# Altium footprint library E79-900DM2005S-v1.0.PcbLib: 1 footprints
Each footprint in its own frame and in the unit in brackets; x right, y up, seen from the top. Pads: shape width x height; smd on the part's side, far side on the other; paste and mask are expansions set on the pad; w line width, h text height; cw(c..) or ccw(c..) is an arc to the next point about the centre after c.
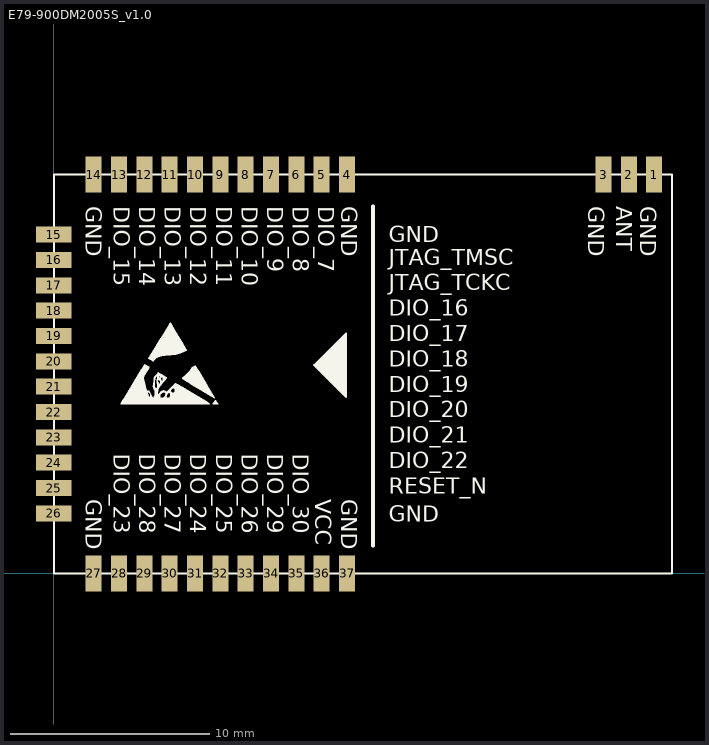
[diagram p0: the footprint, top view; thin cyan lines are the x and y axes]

## E79-900DM2005S_v1.0 [mil]
pads (1585):
  round 0.5 on Top Overlay: 1(132.13,335.44) 1(132.63,335.94) 1(132.63,336.44) 1(133.13,336.94) 1(133.13,337.44) 1(133.63,337.94) 1(134.13,338.44) 1(134.13,338.94) 1(134.63,339.44) 1(134.63,339.94) 1(135.13,340.44) 1(135.63,341.44) 1(135.63,340.94) 1(136.13,341.94) 1(136.13,342.44) 1(136.63,342.94) 1(137.13,343.44) 1(137.13,343.94) 1(137.63,344.44) 1(137.63,344.94) 1(138.13,345.44) 1(138.63,345.94) 1(138.63,346.44) 1(139.13,346.94) 1(139.63,347.94) 1(139.63,347.44) 1(140.13,348.44) 1(140.13,348.94) 1(140.63,349.44) 1(141.13,349.94) 1(141.13,350.44) 1(141.63,350.94) 1(141.63,351.44) 1(142.13,351.94) 1(142.63,352.44) 1(142.63,352.94) 1(143.13,353.44) 1(143.13,353.94) 1(143.63,354.44) 1(144.13,354.94) 1(144.13,355.44) 1(144.63,355.94) 1(144.63,356.44) 1(145.13,356.94) 1(145.63,357.44) 1(145.63,357.94) 1(146.13,358.44) 1(146.13,358.94) 1(146.63,359.44) 1(147.13,359.94) 1(147.13,360.44) 1(147.63,360.94) 1(147.63,361.44) 1(148.13,361.94) 1(148.63,362.44) 1(148.63,362.94) 1(149.13,363.44) 1(149.13,363.94) 1(149.63,364.44) 1(150.13,365.44) 1(150.13,364.94) 1(150.63,365.94) 1(150.63,366.44) 1(151.13,366.94) 1(151.63,367.44) 1(151.63,367.94) 1(152.13,368.44) 1(152.13,368.94) 1(152.63,369.44) 1(153.13,369.94) 1(153.13,370.44) 1(153.63,370.94) 1(153.63,371.44) 1(154.13,371.94) 1(154.63,372.44) 1(154.63,372.94) 1(155.13,373.44) 1(155.13,373.94) 1(155.63,374.44) 1(156.13,375.44) 1(156.13,374.94) 1(156.63,375.94) 1(156.63,376.44) 1(157.13,376.94) 1(157.63,377.44) 1(157.63,377.94) 1(158.13,378.44) 1(158.63,378.94) 1(158.63,379.44) 1(159.13,379.94) 1(159.13,380.44) 1(159.63,380.94) 1(160.13,381.44) 1(160.13,381.94) 1(160.63,382.44) 1(160.63,382.94) 1(161.13,383.44) 1(161.63,383.94) 1(161.63,384.44) 1(162.13,384.94) 1(162.13,385.44) 1(162.63,385.94) 1(163.13,386.44) 1(163.13,386.94) 1(163.63,387.44) 1(163.63,387.94) 1(164.13,388.44) 1(164.63,389.44) 1(164.63,388.94) 1(165.13,389.94) 1(165.13,390.44) 1(165.63,390.94) 1(166.13,391.44) 1(166.13,391.94) 1(166.63,392.44) 1(166.63,392.94) 1(167.13,393.44) 1(167.63,393.94) 1(167.63,394.44) 1(168.13,394.94) 1(168.13,395.44) 1(168.63,395.94) 1(169.13,396.44) 1(169.13,396.94) 1(169.63,397.94) 1(169.63,397.44) 1(170.13,398.44) 1(170.63,398.94) 1(170.63,399.44) 1(171.13,399.94) 1(171.63,400.44) 1(171.63,400.94) 1(172.13,401.44) 1(172.13,401.94) 1(172.63,402.44) 1(173.13,402.94) 1(173.13,403.44) 1(173.63,403.94) 1(173.63,404.44) 1(174.13,404.94) 1(174.63,405.44) 1(174.63,405.94) 1(175.13,406.44) 1(175.13,406.94) 1(175.63,407.44) 1(176.13,407.94) 1(176.13,408.44) 1(176.63,408.94) 1(176.63,409.44) 1(177.13,409.94) 1(177.63,382.94) 1(177.63,383.44) 1(177.63,383.94) 1(177.63,384.44) 1(177.63,384.94) 1(177.63,385.44) 1(177.63,385.94) 1(177.63,386.44) 1(177.63,386.94) 1(177.63,387.44) 1(177.63,387.94) 1(177.63,388.44) 1(177.63,388.94) 1(177.63,410.44) 1(177.63,410.94) 1(178.13,380.44) 1(178.13,380.94) 1(178.13,381.44) 1(178.13,381.94) 1(178.13,382.44) 1(178.13,389.44) 1(178.13,389.94) 1(178.13,390.44) 1(178.13,411.44) 1(178.13,411.94) 1(178.63,378.44) 1(178.63,378.94) 1(178.63,379.44) 1(178.63,379.94) 1(178.63,390.94) 1(178.63,391.44) 1(178.63,412.44) 1(179.13,376.94) 1(179.13,377.44) 1(179.13,377.94) 1(179.13,391.94) 1(179.13,392.44) 1(179.13,412.94) 1(179.63,375.44) 1(179.63,376.44) 1(179.63,392.94) 1(179.63,412.94) 1(179.63,374.94) 1(179.63,375.94) 1(180.13,372.94) 1(180.13,373.94) 1(180.13,393.44) 1(180.13,393.94) 1(180.13,373.44) 1(180.13,374.44) 1(180.63,370.94) 1(180.63,371.44) 1(180.63,371.94) 1(180.63,372.44) 1(180.63,394.44) 1(180.63,412.44) 1(181.13,368.94) 1(181.13,369.44) 1(181.13,369.94) 1(181.13,370.44) 1(181.13,394.94) 1(181.13,395.44) 1(181.13,411.94) 1(181.63,366.44) 1(181.63,366.94) 1(181.63,367.44) 1(181.63,367.94) 1(181.63,368.44) 1(181.63,395.94) 1(181.63,396.44) 1(182.13,364.94) 1(182.13,365.44) 1(182.13,365.94) 1(182.13,396.94) 1(182.13,411.44) 1(182.63,362.94) 1(182.63,363.44) 1(182.63,363.94) 1(182.63,364.44) 1(182.63,397.44) 1(182.63,397.94) 1(183.13,361.94) 1(183.13,362.44) 1(183.13,398.44) 1(183.13,410.94) 1(183.63,361.44) 1(183.63,398.94) 1(183.63,399.44) 1(183.63,410.44) 1(184.13,399.94) 1(184.63,400.44) 1(184.63,400.94) 1(184.63,409.94) 1(185.13,401.44) 1(185.63,354.44) 1(185.63,354.94) 1(185.63,355.44) 1(185.63,355.94) 1(185.63,356.44) 1(185.63,356.94) 1(185.63,357.44) 1(185.63,357.94) 1(185.63,401.94) 1(185.63,402.44) 1(185.63,409.44) 1(186.13,352.44) 1(186.13,352.94) 1(186.13,353.44) 1(186.13,353.94) 1(186.13,358.44) 1(186.13,358.94) 1(186.13,402.94) 1(186.13,408.94) 1(186.63,351.44) 1(186.63,351.94) 1(186.63,358.94) 1(186.63,403.94) 1(186.63,424.94) 1(186.63,403.44) 1(187.13,350.44) 1(187.13,350.94) 1(187.13,404.44) 1(187.13,408.44) 1(187.13,424.44) 1(187.13,425.44) 1(187.63,349.44) 1(187.63,349.94) 1(187.63,358.44) 1(187.63,404.94) 1(187.63,405.44) 1(187.63,425.94) 1(187.63,426.44) 1(188.13,357.94) 1(188.13,360.44) 1(188.13,360.94) 1(188.13,405.94) 1(188.13,406.44) 1(188.13,407.94) 1(188.13,423.94) 1(188.13,426.94) 1(188.63,357.44) 1(188.63,359.44) 1(188.63,359.94) 1(188.63,406.94) 1(188.63,407.44) 1(188.63,427.44) 1(188.63,427.94) 1(189.13,356.44) 1(189.13,356.94) 1(189.13,358.44) 1(189.13,358.94) 1(189.13,428.44) 1(189.13,428.94) 1(189.63,355.44) 1(189.63,355.94) 1(189.63,357.44) 1(189.63,357.94) 1(189.63,423.44) 1(189.63,429.44) 1(190.13,349.44) 1(190.13,349.94) 1(190.13,354.44) 1(190.13,354.94) 1(190.13,356.44) 1(190.13,356.94) 1(190.13,429.94) 1(190.13,430.44) 1(190.63,350.44) 1(190.63,353.94) 1(190.63,355.94) 1(190.63,350.94) 1(190.63,351.44) 1(190.63,351.94) 1(190.63,352.44) 1(190.63,352.94) 1(190.63,353.44) 1(190.63,355.44) 1(190.63,422.94) 1(190.63,430.94) 1(190.63,431.44) 1(191.13,354.44) 1(191.13,353.94) 1(191.13,354.94) 1(191.13,431.94) 1(191.63,432.94) 1(191.63,352.94) 1(191.63,353.44) 1(191.63,422.44) 1(191.63,432.44) 1(192.13,433.44) 1(192.13,351.94) 1(192.13,352.44) 1(192.13,421.94) 1(192.63,433.94) 1(192.63,350.94) 1(192.63,351.44) 1(192.63,434.44) 1(193.13,350.44) 1(193.13,421.44) 1(193.13,434.94) 1(193.13,435.44) 1(193.63,349.94) 1(193.63,435.94) 1(193.63,349.44) 1(194.13,348.44) 1(194.13,420.94) 1(194.13,436.44) 1(194.13,436.94) 1(194.13,348.94) 1(194.63,347.94) 1(194.63,420.44) 1(194.63,437.44) 1(194.63,437.94) 1(195.13,347.44) 1(195.13,438.44) 1(195.63,346.94) 1(195.63,369.94) 1(195.63,370.44) 1(195.63,370.94) 1(195.63,419.94) 1(195.63,438.94) 1(195.63,439.44) 1(196.13,367.94) 1(196.13,368.44) 1(196.13,368.94) 1(196.13,369.44) 1(196.13,371.44) 1(196.13,371.94) 1(196.13,372.44) 1(196.13,372.94) 1(196.13,373.44) 1(196.13,373.94) 1(196.13,439.94) 1(196.13,440.44) 1(196.63,346.94) 1(196.63,366.94) 1(196.63,367.44) 1(196.63,374.44) 1(196.63,374.94) 1(196.63,375.44) 1(196.63,375.94) 1(196.63,376.44) 1(196.63,440.94) 1(197.13,347.44) 1(197.13,347.94) 1(197.13,365.94) 1(197.13,366.44) 1(197.13,376.94) 1(197.13,377.44) 1(197.13,377.94) 1(197.13,378.44) 1(197.13,378.94) 1(197.13,379.44) 1(197.13,379.94) 1(197.13,380.44) 1(197.13,380.94) 1(197.13,381.44) 1(197.13,381.94) 1(197.13,382.44) 1(197.13,382.94) 1(197.13,383.44) 1(197.13,383.94) 1(197.13,384.44) 1(197.13,384.94) 1(197.13,419.94) 1(197.13,441.44) 1(197.13,441.94) 1(197.63,348.44) 1(197.63,364.94) 1(197.63,365.44) 1(197.63,385.44) 1(197.63,385.94) 1(197.63,386.44) 1(197.63,420.44) 1(197.63,420.94) 1(197.63,442.44) 1(198.13,349.44) 1(198.13,364.44) 1(198.13,348.94) 1(198.13,363.94) 1(198.13,386.94) 1(198.13,387.44) 1(198.13,421.44) 1(198.13,421.94) 1(198.13,442.94) 1(198.13,443.44) 1(198.63,349.94) 1(198.63,362.94) 1(198.63,350.44) 1(198.63,363.44) 1(198.63,387.94) 1(198.63,422.44) 1(198.63,443.94) 1(198.63,444.44) 1(199.13,362.44) 1(199.13,374.94) 1(199.13,375.94) 1(199.13,350.94) 1(199.13,351.44) 1(199.13,351.94) 1(199.13,352.44) 1(199.13,352.94) 1(199.13,361.44) 1(199.13,361.94) 1(199.13,368.94) 1(199.13,369.44) 1(199.13,369.94) 1(199.13,370.44) 1(199.13,370.94) 1(199.13,371.44) 1(199.13,371.94) 1(199.13,372.44) 1(199.13,372.94) 1(199.13,373.44) 1(199.13,373.94) 1(199.13,374.44) 1(199.13,375.44) 1(199.13,376.44) 1(199.13,376.94) 1(199.13,377.44) 1(199.13,377.94) 1(199.13,388.44) 1(199.13,422.94) 1(199.13,444.94) 1(199.63,356.44) 1(199.63,367.94) 1(199.63,381.94) 1(199.63,353.44) 1(199.63,353.94) 1(199.63,354.44) 1(199.63,354.94) 1(199.63,355.44) 1(199.63,355.94) 1(199.63,356.94) 1(199.63,357.44) 1(199.63,358.44) 1(199.63,358.94) 1(199.63,359.44) 1(199.63,359.94) 1(199.63,360.44) 1(199.63,360.94) 1(199.63,368.44) 1(199.63,378.44) 1(199.63,378.94) 1(199.63,379.44) 1(199.63,379.94) 1(199.63,380.44) 1(199.63,380.94) 1(199.63,381.44) 1(199.63,382.44) 1(199.63,382.94) 1(199.63,388.94) 1(199.63,423.44) 1(199.63,445.44) 1(199.63,445.94) 1(200.13,357.94) 1(200.13,366.94) 1(200.13,367.44) 1(200.13,383.44) 1(200.13,383.94) 1(200.13,384.44) 1(200.13,384.94) 1(200.13,385.44) 1(200.13,389.44) 1(200.13,423.94) 1(200.13,446.44) 1(200.63,366.44) 1(200.63,385.94) 1(200.63,386.44) 1(200.63,386.94) 1(200.63,389.94) 1(200.63,424.44) 1(200.63,446.94) 1(200.63,447.44) 1(201.13,365.94) 1(201.13,387.44) 1(201.13,387.94) 1(201.13,390.44) 1(201.13,424.94) 1(201.13,448.44) 1(201.13,447.94) 1(201.63,390.94) 1(201.63,425.44) 1(201.63,448.94) 1(201.63,388.44) 1(202.13,391.44) 1(202.13,449.44) 1(202.13,388.94) 1(202.13,449.94) 1(202.63,389.44) 1(202.63,391.94) 1(202.63,425.94) 1(202.63,450.44) 1(202.63,450.94) 1(203.13,365.94) 1(203.13,389.94) 1(203.13,392.44) 1(203.13,426.44) 1(203.13,451.44) 1(203.63,366.44) 1(203.63,366.94) 1(203.63,375.94) 1(203.63,376.44) 1(203.63,376.94) 1(203.63,377.44) 1(203.63,377.94) 1(203.63,378.44) 1(203.63,378.94) 1(203.63,379.44) 1(203.63,379.94) 1(203.63,380.44) 1(203.63,380.94) 1(203.63,381.44) 1(203.63,381.94) 1(203.63,382.44) 1(203.63,382.94) 1(203.63,392.94) 1(203.63,451.94) 1(203.63,452.44) 1(204.13,367.44) 1(204.13,367.94) 1(204.13,368.44) 1(204.13,368.94) 1(204.13,369.44) 1(204.13,369.94) 1(204.13,370.44) 1(204.13,370.94) 1(204.13,371.94) 1(204.13,372.44) 1(204.13,372.94) 1(204.13,373.44) 1(204.13,373.94) 1(204.13,374.44) 1(204.13,374.94) 1(204.13,375.44) 1(204.13,383.44) 1(204.13,383.94) 1(204.13,384.44) 1(204.13,384.94) 1(204.13,385.44) 1(204.13,385.94) 1(204.13,386.44) 1(204.13,388.94) 1(204.13,389.44) 1(204.13,389.94) 1(204.13,393.44) 1(204.13,393.94) 1(204.13,426.94) 1(204.13,452.94) 1(204.13,453.44) 1(204.63,371.44) 1(204.63,386.94) 1(204.63,387.44) 1(204.63,387.94) 1(204.63,388.44) 1(204.63,394.44) 1(204.63,453.94) 1(205.13,379.94) 1(205.13,394.94) 1(205.13,395.44) 1(205.13,427.44) 1(205.13,454.44) 1(205.13,454.94) 1(205.63,354.94) 1(205.63,355.94) 1(205.63,356.94) 1(205.63,381.44) 1(205.63,396.44) 1(205.63,455.44) 1(205.63,354.44) 1(205.63,355.44) 1(205.63,356.44) 1(205.63,357.44) 1(205.63,357.94) 1(205.63,358.44) 1(205.63,358.94) 1(205.63,359.44) 1(205.63,359.94) 1(205.63,377.94) 1(205.63,378.44) 1(205.63,378.94) 1(205.63,379.44) 1(205.63,380.44) 1(205.63,380.94) 1(205.63,381.94) 1(205.63,395.94) 1(205.63,396.94) 1(206.13,362.94) 1(206.13,396.94) 1(206.13,455.94) 1(206.13,353.94) 1(206.13,360.44) 1(206.13,360.94) 1(206.13,361.44) 1(206.13,361.94) 1(206.13,362.44) 1(206.13,376.94) 1(206.13,377.44) 1(206.13,382.44) 1(206.13,456.44) 1(206.63,363.44) 1(206.63,396.44) 1(206.63,353.94) 1(206.63,363.94) 1(206.63,364.44) 1(206.63,364.94) 1(206.63,376.44) 1(206.63,427.94) 1(206.63,456.94) 1(206.63,457.44) 1(207.13,389.44) 1(207.13,365.44) 1(207.13,365.94) 1(207.13,375.44) 1(207.13,375.94) 1(207.13,387.44) 1(207.13,387.94) 1(207.13,388.44) 1(207.13,388.94) 1(207.13,457.94) 1(207.63,354.44) 1(207.63,366.44) 1(207.63,366.94) 1(207.63,386.94) 1(207.63,389.94) 1(207.63,390.44) 1(207.63,395.94) 1(207.63,428.44) 1(207.63,458.44) 1(207.63,458.94) 1(208.13,354.94) 1(208.13,367.44) 1(208.13,459.44) 1(208.13,367.94) 1(208.63,355.44) 1(208.63,368.94) 1(208.63,390.94) 1(208.63,395.44) 1(208.63,459.94) 1(208.63,460.44) 1(208.63,368.44) 1(208.63,382.44) 1(209.13,355.94) 1(209.13,369.44) 1(209.13,369.94) 1(209.13,386.94) 1(209.13,387.44) 1(209.13,390.94) 1(209.13,428.94) 1(209.13,460.94) 1(209.13,461.44) 1(209.13,381.94) 1(209.63,356.44) 1(209.63,370.44) 1(209.63,388.44) 1(209.63,389.44) 1(209.63,390.44) 1(209.63,394.94) 1(209.63,350.44) 1(209.63,356.94) 1(209.63,381.44) 1(209.63,387.94) 1(209.63,388.94) 1(209.63,389.94) 1(209.63,461.94) 1(210.13,346.94) 1(210.13,347.94) 1(210.13,348.94) 1(210.13,349.94) 1(210.13,357.44) 1(210.13,375.44) 1(210.13,380.94) 1(210.13,462.44) 1(210.13,347.44) 1(210.13,348.44) 1(210.13,349.44) 1(210.13,350.94) 1(210.13,351.44) 1(210.13,351.94) 1(210.13,352.44) 1(210.13,352.94) 1(210.13,370.94) 1(210.13,371.44) 1(210.13,380.44) 1(210.13,394.44) 1(210.13,462.94) 1(210.63,375.94) 1(210.63,463.94) 1(210.63,353.44) 1(210.63,353.94) 1(210.63,357.94) 1(210.63,358.44) 1(210.63,371.94) 1(210.63,376.44) 1(210.63,376.94) 1(210.63,379.44) 1(210.63,379.94) 1(210.63,463.44) 1(211.13,382.94) 1(211.13,354.44) 1(211.13,354.94) 1(211.13,358.94) 1(211.13,372.44) 1(211.13,377.44) 1(211.13,377.94) 1(211.13,378.44) 1(211.13,378.94) 1(211.13,383.44) 1(211.13,383.94) 1(211.13,384.44) 1(211.13,384.94) 1(211.13,385.44) 1(211.13,385.94) 1(211.13,386.44) 1(211.13,393.94) 1(211.13,429.44) 1(211.13,464.44) 1(211.63,382.44) 1(211.63,355.44) 1(211.63,359.44) 1(211.63,372.94) 1(211.63,373.44) 1(211.63,381.94) 1(211.63,386.94) 1(211.63,387.44) 1(211.63,464.94) 1(211.63,465.44) 1(212.13,355.94) 1(212.13,359.94) 1(212.13,373.94) 1(212.13,380.94) 1(212.13,381.44) 1(212.13,393.44) 1(212.13,465.94) 1(212.13,466.44) 1(212.63,356.44) 1(212.63,360.44) 1(212.63,374.44) 1(212.63,392.94) 1(212.63,466.94) 1(213.13,356.94) 1(213.13,360.94) 1(213.13,374.94) 1(213.13,380.44) 1(213.13,387.94) 1(213.13,429.94) 1(213.13,467.44) 1(213.13,467.94) 1(213.63,375.44) 1(213.63,392.44) 1(213.63,468.44) 1(214.13,357.44) 1(214.13,375.94) 1(214.13,376.44) 1(214.13,468.94) 1(214.13,469.44) 1(214.63,376.94) 1(214.63,380.44) 1(214.63,380.94) 1(214.63,381.44) 1(214.63,381.94) 1(214.63,382.44) 1(214.63,382.94) 1(214.63,383.44) 1(214.63,383.94) 1(214.63,384.44) 1(214.63,384.94) 1(214.63,385.44) 1(214.63,385.94) 1(214.63,386.44) 1(214.63,387.94) 1(214.63,391.94) 1(214.63,469.94) 1(214.63,470.44) 1(215.13,357.94) 1(215.13,377.44) 1(215.13,386.94) 1(215.13,387.44) 1(215.13,391.44) 1(215.13,470.94) 1(215.63,346.94) 1(215.63,361.44) 1(215.63,377.94) 1(215.63,471.44) 1(215.63,471.94) 1(216.13,378.44) 1(216.13,390.94) 1(216.13,430.44) 1(216.13,472.44) 1(216.63,347.44) 1(216.63,361.44) 1(216.63,378.94) 1(216.63,472.94) 1(216.63,473.44) 1(217.13,379.44) 1(217.13,390.44) 1(217.13,473.94) 1(217.13,474.44) 1(217.63,347.94) 1(217.63,379.94) 1(217.63,389.94) 1(217.63,474.94) 1(218.13,348.44) 1(218.13,380.44) 1(218.13,475.44) 1(218.13,475.94) 1(218.63,348.94) 1(218.63,389.44) 1(218.63,357.94) 1(218.63,360.94) 1(218.63,380.94) 1(218.63,476.44) 1(218.63,476.94) 1(219.13,349.44) 1(219.13,349.94) 1(219.13,381.44) 1(219.13,381.94) 1(219.13,388.94) 1(219.13,477.44) 1(219.63,350.44) 1(219.63,357.44) 1(219.63,360.44) 1(219.63,382.44) 1(219.63,430.94) 1(219.63,477.94) 1(219.63,478.44) 1(220.13,350.94) 1(220.13,351.44) 1(220.13,351.94) 1(220.13,352.44) 1(220.13,356.44) 1(220.13,356.94) 1(220.13,359.94) 1(220.13,382.94) 1(220.13,388.44) 1(220.13,478.94) 1(220.63,352.94) 1(220.63,353.44) 1(220.63,353.94) 1(220.63,354.44) 1(220.63,354.94) 1(220.63,355.94) 1(220.63,383.44) 1(220.63,479.94) 1(220.63,355.44) 1(220.63,479.44) 1(221.13,359.44) 1(221.13,383.94) 1(221.13,384.44) 1(221.13,480.44) 1(221.13,480.94) 1(221.13,387.94) 1(221.63,348.44) 1(221.63,348.94) 1(221.63,358.94) 1(221.63,384.94) 1(221.63,387.44) 1(221.63,481.44) 1(222.13,347.94) 1(222.13,349.44) 1(222.13,349.94) 1(222.13,350.44) 1(222.13,358.44) 1(222.13,385.44) 1(222.13,385.94) 1(222.13,481.94) 1(222.13,482.44) 1(222.63,350.94) 1(222.63,351.44) 1(222.63,351.94) 1(222.63,386.44) 1(222.63,386.94) 1(222.63,482.94) 1(222.63,483.44) 1(223.13,347.44) 1(223.13,352.44) 1(223.13,352.94) 1(223.13,358.44) 1(223.13,483.94) 1(223.63,353.44) 1(223.63,353.94) 1(223.63,358.94) 1(223.63,484.44) 1(223.63,484.94) 1(224.13,354.44) 1(224.13,354.94) 1(224.13,359.44) 1(224.13,485.44) 1(224.13,485.94) 1(224.63,486.44) 1(224.63,355.44) 1(224.63,359.94) 1(225.13,486.94) 1(225.13,346.94) 1(225.13,355.94) 1(225.13,360.44) 1(225.13,431.44) 1(225.13,487.44) 1(225.63,356.44) 1(225.63,360.94) 1(225.63,487.94) 1(226.13,356.94) 1(226.13,361.44) 1(226.13,488.44) 1(226.13,488.94) 1(226.63,346.94) 1(226.63,361.94) 1(226.63,489.44) 1(226.63,489.94) 1(227.13,362.44) 1(227.13,490.44) 1(227.63,362.94) 1(227.63,490.94) 1(227.63,491.44) 1(228.13,363.44) 1(228.13,491.94) 1(228.13,492.44) 1(228.63,363.94) 1(228.63,347.44) 1(228.63,492.94) 1(229.13,347.94) 1(229.13,348.44) 1(229.13,356.94) 1(229.13,364.44) 1(229.13,493.44) 1(229.13,493.94) 1(229.63,348.94) 1(229.63,349.44) 1(229.63,349.94) 1(229.63,350.44) 1(229.63,350.94) 1(229.63,351.44) 1(229.63,351.94) 1(229.63,352.44) 1(229.63,352.94) 1(229.63,353.44) 1(229.63,353.94) 1(229.63,354.44) 1(229.63,354.94) 1(229.63,355.44) 1(229.63,355.94) 1(229.63,356.44) 1(229.63,364.94) 1(229.63,494.44) 1(230.13,365.44) 1(230.13,494.94) 1(230.63,360.44) 1(230.63,360.94) 1(230.63,361.44) 1(230.63,365.94) 1(230.63,494.94) 1(231.13,358.94) 1(231.13,359.44) 1(231.13,359.94) 1(231.13,361.94) 1(231.13,362.44) 1(231.13,362.94) 1(231.13,366.44) 1(231.13,493.94) 1(231.13,494.44) 1(231.63,358.44) 1(231.63,363.44) 1(231.63,363.94) 1(231.63,366.94) 1(231.63,431.94) 1(231.63,492.94) 1(231.63,493.44) 1(232.13,364.44) 1(232.13,367.44) 1(232.13,357.94) 1(232.13,492.44) 1(232.63,367.94) 1(232.63,357.44) 1(232.63,364.94) 1(232.63,491.44) 1(232.63,491.94) 1(233.13,368.44) 1(233.13,356.94) 1(233.13,365.44) 1(233.13,490.44) 1(233.13,490.94) 1(233.63,365.94) 1(233.63,368.94) 1(233.63,489.44) 1(233.63,489.94) 1(234.13,369.44) 1(234.13,488.94) 1(234.63,366.44) 1(234.63,369.94) 1(234.63,487.94) 1(234.63,488.44) 1(235.13,370.44) 1(235.13,486.94) 1(235.13,487.44) 1(235.63,370.94) 1(235.63,486.44) 1(236.13,371.44) 1(236.13,485.44) 1(236.13,485.94) 1(236.63,371.94) 1(236.63,484.44) 1(236.63,484.94) 1(237.13,356.94) 1(237.13,366.44) 1(237.13,372.44) 1(237.13,432.44) 1(237.13,483.44) 1(237.13,483.94) 1(237.63,357.44) 1(237.63,372.94) 1(237.63,482.94) 1(238.13,365.94) 1(238.13,373.44) 1(238.13,481.94) 1(238.13,482.44) 1(238.63,357.94) 1(238.63,358.44) 1(238.63,365.44) 1(238.63,373.94) 1(238.63,480.94) 1(238.63,481.44) 1(239.13,358.94) 1(239.13,359.44) 1(239.13,359.94) 1(239.13,360.44) 1(239.13,360.94) 1(239.13,361.44) 1(239.13,361.94) 1(239.13,362.44) 1(239.13,362.94) 1(239.13,363.44) 1(239.13,363.94) 1(239.13,364.44) 1(239.13,364.94) 1(239.13,374.44) 1(239.13,479.94) 1(239.13,480.44) 1(239.63,374.94) 1(239.63,479.44) 1(240.13,375.44) 1(240.13,478.44) 1(240.13,478.94) 1(240.63,477.94) 1(240.63,432.94) 1(240.63,477.44) 1(241.13,375.44) 1(241.13,476.94) 1(241.63,475.94) 1(241.63,476.44) 1(242.13,374.94) 1(242.13,474.94) 1(242.13,475.44) 1(242.63,433.44) 1(242.63,474.44) 1(243.13,473.44) 1(243.13,473.94) 1(243.13,374.44) 1(243.63,373.94) 1(243.63,472.44) 1(243.63,472.94) 1(244.13,471.44) 1(244.13,471.94) 1(244.63,373.44) 1(244.63,433.94) 1(244.63,470.94) 1(245.13,469.94) 1(245.13,470.44) 1(245.63,372.94) 1(245.63,468.94) 1(245.63,469.44) 1(246.13,434.44) 1(246.13,468.44) 1(246.63,372.44) 1(246.63,467.44) 1(246.63,467.94) 1(247.13,371.94) 1(247.13,466.44) 1(247.13,466.94) 1(247.63,434.94) 1(247.63,465.44) 1(247.63,465.94) 1(248.13,371.44) 1(248.13,464.94) 1(248.63,463.94) 1(248.63,464.44) 1(249.13,370.94) 1(249.13,435.44) 1(249.13,462.94) 1(249.13,463.44) 1(249.63,370.44) 1(249.63,462.44) 1(250.13,435.94) 1(250.13,461.44) 1(250.13,461.94) 1(250.63,369.94) 1(250.63,460.44) 1(250.63,460.94) 1(251.13,459.94) 1(251.63,369.44) 1(251.63,436.44) 1(251.63,458.94) 1(251.63,459.44) 1(252.13,457.94) 1(252.13,458.44) 1(252.63,368.94) 1(252.63,436.94) 1(252.63,456.94) 1(252.63,457.44) 1(253.13,368.44) 1(253.13,385.44) 1(253.13,456.44) 1(253.63,384.94) 1(253.63,385.94) 1(253.63,455.44) 1(253.63,455.94) 1(254.13,367.94) 1(254.13,454.94) 1(254.13,384.44) 1(254.13,386.44) 1(254.13,437.44) 1(254.13,454.44) 1(254.63,386.94) 1(254.63,453.94) 1(255.13,367.44) 1(255.13,383.94) 1(255.13,387.44) 1(255.13,437.94) 1(255.13,452.94) 1(255.13,453.44) 1(255.63,366.94) 1(255.63,387.94) 1(255.63,451.94) 1(255.63,452.44) 1(256.13,383.44) 1(256.13,438.44) 1(256.13,450.94) 1(256.13,451.44) 1(256.63,366.44) 1(256.63,388.44) 1(256.63,450.44) 1(257.13,388.94) 1(257.13,438.94) 1(257.13,449.94) 1(257.13,382.94) 1(257.13,449.44) 1(257.63,365.94) 1(257.63,389.44) 1(257.63,382.44) 1(257.63,448.94) 1(258.13,365.44) 1(258.13,389.94) 1(258.13,439.44) 1(258.13,447.94) 1(258.13,448.44) 1(258.63,381.94) 1(258.63,390.44) 1(258.63,446.94) 1(258.63,447.44) 1(259.13,364.94) 1(259.13,439.94) 1(259.13,446.44) 1(259.63,381.44) 1(259.63,390.94) 1(259.63,445.44) 1(259.63,445.94) 1(260.13,364.44) 1(260.13,380.94) 1(260.13,391.44) 1(260.13,440.44) 1(260.13,444.44) 1(260.13,444.94) 1(260.63,391.94) 1(260.63,443.44) 1(260.63,443.94) 1(261.13,363.94) 1(261.13,380.44) 1(261.13,392.44) 1(261.13,440.94) 1(261.13,442.94) 1(261.63,441.94) 1(261.63,363.44) 1(261.63,392.94) 1(261.63,442.44) 1(262.13,441.44) 1(262.13,379.94) 1(262.13,393.44) 1(262.63,362.94) 1(262.63,379.44) 1(262.63,393.94) 1(263.13,394.44) 1(263.63,362.44) 1(263.63,378.94) 1(263.63,394.94) 1(264.13,361.94) 1(264.13,395.44) 1(264.63,378.44) 1(264.63,395.94) 1(265.13,361.44) 1(265.13,377.94) 1(265.13,396.44) 1(265.63,396.94) 1(266.13,360.94) 1(266.13,377.44) 1(266.13,397.44) 1(266.63,360.44) 1(266.63,376.94) 1(266.63,397.94) 1(267.13,398.44) 1(267.63,359.94) 1(267.63,376.44) 1(267.63,398.94) 1(268.13,399.44) 1(268.13,399.94) 1(268.63,359.44) 1(268.63,375.94) 1(268.63,400.44) 1(269.13,375.44) 1(269.13,358.94) 1(269.13,400.94) 1(269.63,401.44) 1(269.63,401.94) 1(270.13,358.44) 1(270.13,374.94) 1(270.13,402.44) 1(270.63,402.94) 1(270.63,403.44) 1(271.13,357.94) 1(271.13,374.44) 1(271.13,403.94) 1(271.13,404.44) 1(271.63,357.44) 1(271.63,373.94) 1(271.63,404.94) 1(272.13,405.94) 1(272.13,405.44) 1(272.63,373.44) 1(272.63,406.44) 1(272.63,406.94) 1(272.63,356.94) 1(273.13,407.44) 1(273.63,356.44) 1(273.63,372.94) 1(274.13,355.94) 1(274.13,372.44) 1(274.13,407.94) 1(275.13,355.44) 1(275.13,371.94) 1(275.63,408.44) 1(276.13,354.94) 1(276.13,371.44) 1(276.63,354.44) 1(276.63,370.94) 1(276.63,408.94) 1(277.63,353.94) 1(277.63,370.44) 1(277.63,409.44) 1(278.13,369.94) 1(278.63,353.44) 1(278.63,409.94) 1(279.13,352.94) 1(279.13,369.44) 1(280.13,352.44) 1(280.13,368.94) 1(280.13,409.44) 1(280.13,409.94) 1(280.63,368.44) 1(280.63,408.94) 1(281.13,351.94) 1(281.13,407.94) 1(281.13,408.44) 1(281.63,351.44) 1(281.63,367.94) 1(281.63,407.44) 1(282.13,406.44) 1(282.13,406.94) 1(282.63,350.94) 1(282.63,367.44) 1(282.63,405.44) 1(282.63,405.94) 1(283.13,366.94) 1(283.13,404.94) 1(283.63,350.44) 1(283.63,403.94) 1(283.63,404.44) 1(284.13,349.94) 1(284.13,403.44) 1(284.13,366.44) 1(284.13,402.94) 1(284.63,402.44) 1(285.13,349.44) 1(285.13,365.94) 1(285.13,401.44) 1(285.13,401.94) 1(285.63,365.44) 1(285.63,400.94) 1(286.13,399.94) 1(286.13,400.44) 1(286.13,348.94) 1(286.63,364.94) 1(286.63,398.94) 1(286.63,399.44) 1(286.63,348.44) 1(287.13,364.44) 1(287.13,398.44) 1(287.63,347.94) 1(287.63,397.94) 1(287.63,397.44) 1(288.13,347.44) 1(288.13,363.94) 1(288.13,396.44) 1(288.13,396.94) 1(288.63,395.94) 1(289.13,346.94) 1(289.13,363.44) 1(289.13,394.94) 1(289.13,395.44) 1(289.63,362.94) 1(289.63,393.94) 1(289.63,394.44) 1(290.13,346.44) 1(290.13,393.44) 1(290.63,362.44) 1(290.63,392.44) 1(290.63,392.94) 1(291.13,345.94) 1(291.13,391.44) 1(291.13,391.94) 1(291.63,345.44) 1(291.63,361.94) 1(291.63,390.94) 1(292.13,389.94) 1(292.13,361.44) 1(292.13,390.44) 1(292.63,344.94) 1(292.63,388.94) 1(292.63,389.44) 1(293.13,344.44) 1(293.13,360.94) 1(293.13,387.94) 1(293.13,388.44) 1(293.63,387.44) 1(294.13,343.94) 1(294.13,360.44) 1(294.13,386.44) 1(294.13,386.94) 1(294.63,359.94) 1(294.63,385.44) 1(294.63,385.94) 1(295.13,343.44) 1(295.13,384.94) 1(295.63,342.94) 1(295.63,359.44) 1(295.63,383.94) 1(295.63,384.44) 1(296.13,382.94) 1(296.13,383.44) 1(296.63,342.44) 1(296.63,358.94) 1(296.63,382.44) 1(297.13,358.44) 1(297.13,381.44) 1(297.13,381.94) 1(297.63,341.94) 1(297.63,380.44) 1(297.63,380.94) 1(298.13,341.44) 1(298.13,357.94) 1(298.13,379.44) 1(298.13,379.94) 1(298.63,378.94) 1(299.13,340.94) 1(299.13,357.44) 1(299.13,377.94) 1(299.13,378.44) 1(299.63,356.94) 1(299.63,376.94) 1(299.63,377.44) 1(300.13,340.44) 1(300.13,376.44) 1(300.63,339.94) 1(300.63,356.44) 1(300.63,375.44) 1(300.63,375.94) 1(301.13,374.94) 1(301.13,374.44) 1(301.63,339.44) 1(301.63,373.44) 1(301.63,355.94) 1(301.63,373.94) 1(302.13,372.94) 1(302.63,338.94) 1(302.63,355.44) 1(302.63,371.94) 1(302.63,372.44) 1(303.13,338.44) 1(303.13,354.94) 1(303.13,370.94) 1(303.13,371.44) 1(303.63,369.94) 1(303.63,370.44) 1(304.13,337.94) 1(304.13,354.44) 1(304.13,369.44) 1(304.63,337.44) 1(304.63,353.94) 1(304.63,368.44) 1(304.63,368.94) 1(305.13,367.44) 1(305.13,367.94) 1(305.63,366.94) 1(305.63,336.94) 1(305.63,353.44) 1(306.13,366.44) 1(306.13,365.94) 1(306.63,336.44) 1(306.63,352.94) 1(306.63,364.94) 1(306.63,365.44) 1(307.13,335.94) 1(307.13,363.94) 1(307.13,364.44) 1(307.63,352.44) 1(307.63,363.44) 1(308.13,335.44) 1(308.13,351.94) 1(308.13,362.44) 1(308.13,362.94) 1(308.63,361.44) 1(308.63,361.94) 1(309.13,351.44) 1(309.13,360.94) 1(309.63,359.94) 1(309.63,360.44) 1(310.13,350.94) 1(310.13,358.94) 1(310.13,359.44) 1(310.63,358.44) 1(311.13,350.44) 1(311.13,357.44) 1(311.13,357.94) 1(311.63,349.94) 1(311.63,356.44) 1(311.63,356.94) 1(312.13,355.94) 1(312.63,349.44) 1(312.63,354.94) 1(312.63,355.44) 1(313.13,354.44) 1(313.13,353.94) 1(313.63,334.94) 1(313.63,335.44) 1(313.63,348.94) 1(313.63,353.44) 1(314.13,335.94) 1(314.13,348.44) 1(314.13,352.44) 1(314.13,352.94) 1(314.63,336.44) 1(314.63,351.44) 1(314.63,351.94) 1(315.13,336.94) 1(315.13,347.94) 1(315.13,350.94) 1(315.63,337.44) 1(315.63,349.94) 1(315.63,350.44) 1(316.13,337.94) 1(316.13,338.44) 1(316.13,347.44) 1(316.13,349.44) 1(316.13,348.94) 1(316.63,338.94) 1(316.63,348.44) 1(317.13,347.44) 1(317.13,339.44) 1(317.13,346.94) 1(317.13,347.94) 1(317.63,339.94) 1(317.63,346.94) 1(318.13,340.44) 1(318.63,340.94) 1(318.63,341.44) 1(319.13,341.94) 1(319.63,341.94) 1(320.13,340.94) 1(320.13,341.44) 1(320.63,340.44) 1(321.13,339.94) 1(321.13,339.44) 1(321.63,338.94) 1(322.13,337.94) 1(322.13,338.44) 1(322.63,337.44) 1(323.13,336.44) 1(323.13,336.94) 1(323.63,335.94) 1(324.13,334.94) 1(324.13,335.44)
  rect 31.5x70.87 smd: 1(1185.04,787.4) 2(1135.04,787.4) 3(1085.04,787.4) 4(578.74,787.4) 5(528.74,787.4) 6(478.74,787.4) 7(428.74,787.4) 8(378.74,787.4) 9(328.74,787.4) 10(278.74,787.4) 11(228.74,787.4) 12(178.74,787.4) 13(128.74,787.4) 14(78.74,787.4) 27(78.74,0) 28(128.74,0) 29(178.74,0) 30(228.74,0) 31(278.74,0) 32(328.74,0) 33(378.74,0) 34(428.74,0) 35(478.74,0) 36(528.74,0) 37(578.74,0)
  rect 70.87x31.5 smd: 15(0,668.7) 16(0,618.7) 17(0,568.7) 18(0,518.7) 19(0,468.7) 20(0,418.7) 21(0,368.7) 22(0,318.7) 23(0,268.7) 24(0,218.7) 25(0,168.7) 26(0,118.7)
Top Overlay:
  drawing of 840 lines, arcs and shapes, not listed
  text "GND" at 1157.48,724.41 h31.5
  text "ANT" at 1110.24,724.41 h31.5
  text "GND" at 1055.12,724.41 h31.5
  text "DIO_14" at 169.03,724.41 h31.5
  text "DIO_13" at 219.42,724.41 h31.5
  text "DIO_12" at 269.81,724.41 h31.5
  text "DIO_11" at 320.21,724.41 h31.5
  text "DIO_10" at 370.6,724.41 h31.5
  text "DIO_9" at 421,724.41 h31.5
  text "DIO_8" at 471.39,724.41 h31.5
  text "DIO_7" at 521.78,724.41 h31.5
  text "GND" at 566.93,724.41 h31.5
  text "GND" at 566.93,146.7 h31.5
  text "VCC" at 516.54,146.7 h31.5
  text "DIO_30" at 471.39,235.91 h31.5
  text "DIO_29" at 421,235.91 h31.5
  text "DIO_26" at 370.6,235.91 h31.5
  text "DIO_25" at 320.21,235.91 h31.5
  text "DIO_24" at 269.81,235.91 h31.5
  text "DIO_27" at 219.42,235.91 h31.5
  text "DIO_28" at 169.03,235.91 h31.5
  text "DIO_23" at 118.63,235.91 h31.5
  text "GND" at 62.99,146.7 h31.5
  text "DIO_15" at 118.63,724.41 h31.5
  text "GND" at 62.99,724.41 h31.5
  text "RESET_N" at 661.42,157.72 h31.5
  text "DIO_22" at 661.42,207.82 h31.5
  text "GND" at 661.42,653.54 h31.5
  text "DIO_19" at 661.42,358.15 h31.5
  text "DIO_20" at 661.42,308.04 h31.5
  text "DIO_21" at 661.42,257.93 h31.5
  text "GND" at 661.42,102.36 h31.5
  text "DIO_18" at 661.42,408.25 h31.5
  text "DIO_17" at 661.42,458.36 h31.5
  text "DIO_16" at 661.42,508.47 h31.5
  text "JTAG_TCKC" at 661.42,558.58 h31.5
  text "JTAG_TMSC" at 661.42,608.68 h31.5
